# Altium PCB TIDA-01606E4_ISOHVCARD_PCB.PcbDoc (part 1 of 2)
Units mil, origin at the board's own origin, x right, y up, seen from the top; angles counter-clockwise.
Board outline 2900 x 1300 mil, 4 copper layers (Top Layer, Signal Layer 1, Signal Layer 2, Bottom Layer), stack 61.6 mil thick; 82 components, 40 nets, 166 pads, 21 vias.
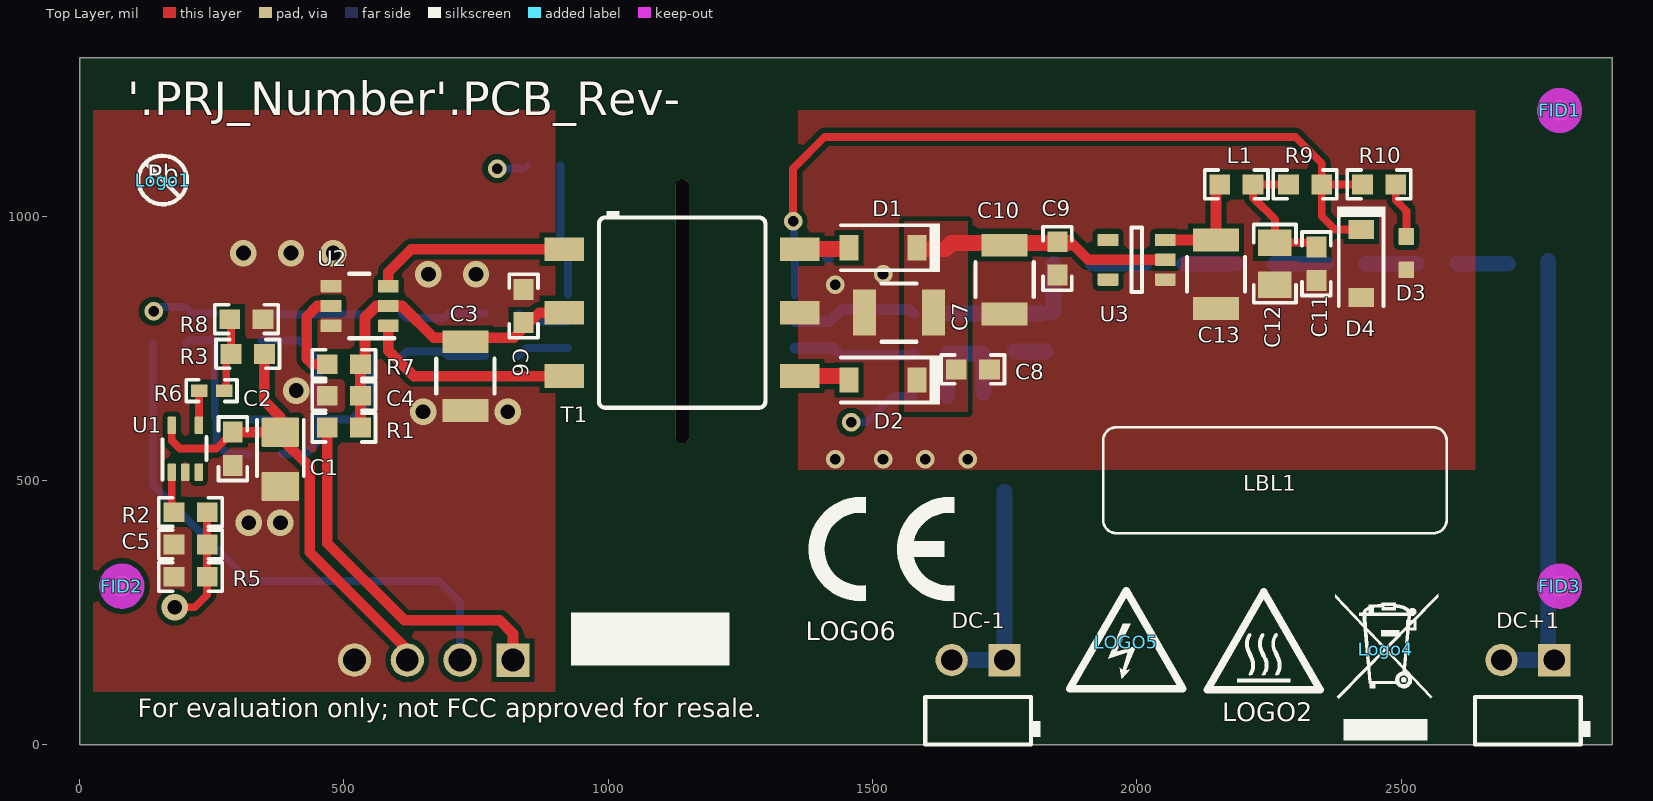
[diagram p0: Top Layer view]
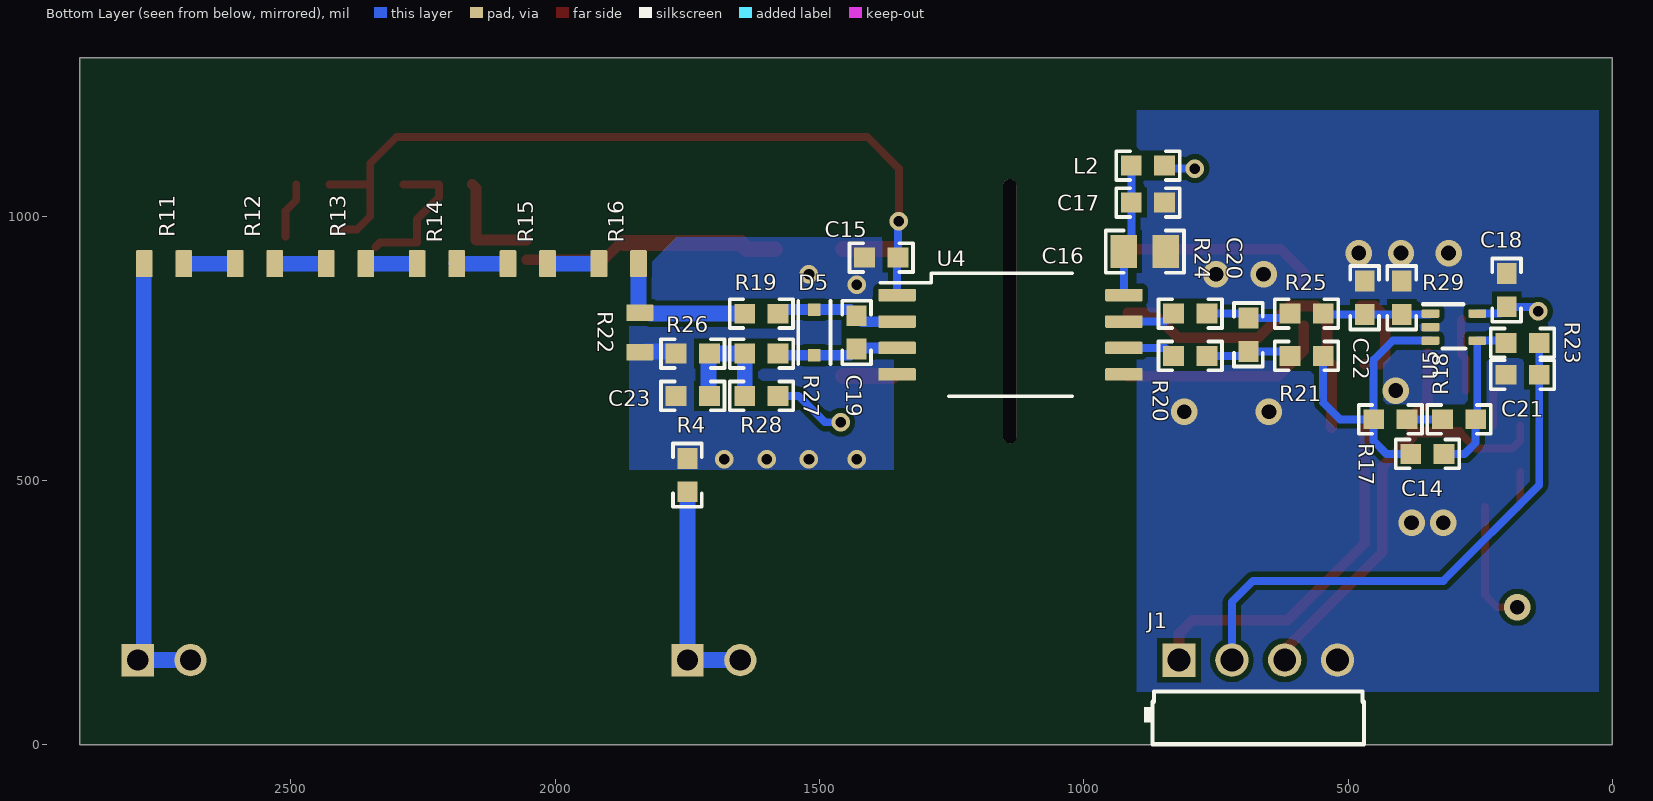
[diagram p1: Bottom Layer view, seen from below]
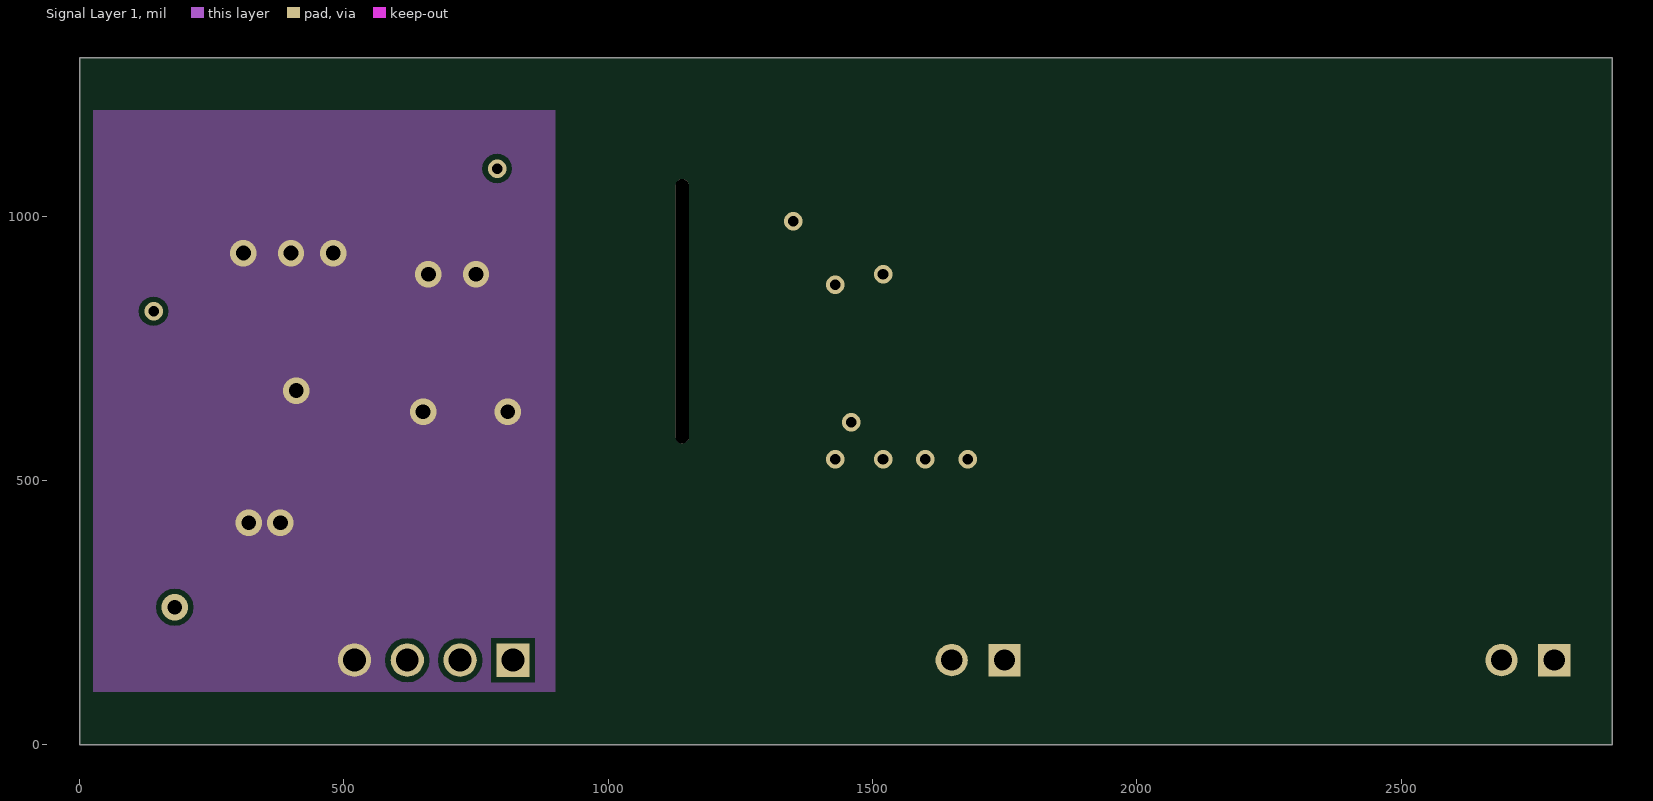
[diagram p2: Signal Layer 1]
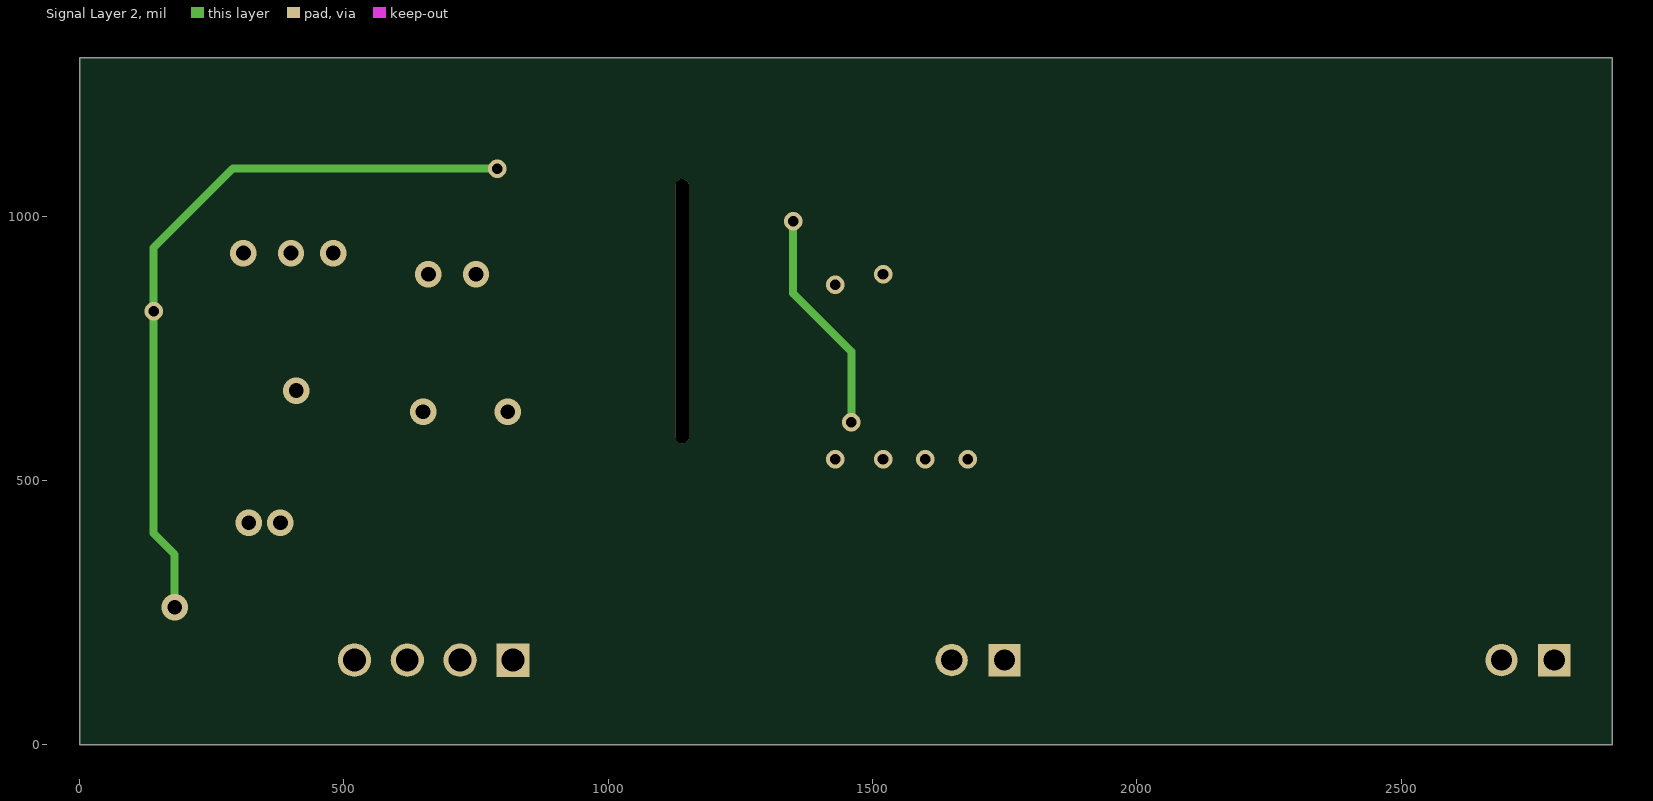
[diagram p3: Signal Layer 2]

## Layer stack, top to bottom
Top Solder: solder mask 0.4, Solder Resist, Dk 3.5
Top Layer: signal copper 1.4
Dielectric 1: prepreg 8, FR-4, Dk 4.2
Signal Layer 1: signal copper 1.4
Dielectric 2: core 40, FR-4, Dk 4.2
Signal Layer 2: signal copper 1.4
Dielectric 3: prepreg 8, FR-4, Dk 4.2
Bottom Layer: signal copper 1.4
Bottom Solder: solder mask 0.4, Solder Resist, Dk 3.5

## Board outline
0,0 2900,0 2900,1300 0,1300

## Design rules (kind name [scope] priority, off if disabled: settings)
AcuteAngle [All] p1: minimum=4.50000000000000E+0001 checktracksonly=FALSE
AssemblyTestPointUsage [All] p1: valid=2
BoardOutlineClearance BoardOutlineClearance_MountingHoles [OnCopper and InComponentClass('Mounting Holes')] p1: gap=40 ignorepadtopadclearanceinfootprint=FALSE
BoardOutlineClearance BoardOutlineClearance_Poly [OnCopper and IsPoly] p2: gap=25 ignorepadtopadclearanceinfootprint=FALSE
BoardOutlineClearance [OnCopper and Not InComponentClass('Logo') and not InComponentClass('FiducialMark') and not InRegion(1000,500,4000,800) and not InPoly] p3: gap=20 ignorepadtopadclearanceinfootprint=FALSE
Clearance Clearance_Keepouts [((IsTrack Or IsArc) And Not InPoly) And IsFree and IsKeepOut vs ((IsTrack Or IsArc) And Not InPoly) And IsFree and IsKeepOut] p1: gap=0 ignorepadtopadclearanceinfootprint=FALSE
Clearance Clearance_Poly [InPolygon] p2: gap=10 ignorepadtopadclearanceinfootprint=FALSE except(0: Arc-Hole Track-Hole SMDPad-Hole THPad-Hole Via-Hole Fill-Hole Poly-Hole Region-Hole Text-Hole)
Clearance Clearance_FiducialMark [IsKeepOut and InComponentClass('FiducialMark') vs IsPad and InComponentClass('FiducialMark')] p3: gap=0 ignorepadtopadclearanceinfootprint=FALSE
Clearance [All] p4: gap=7.87 ignorepadtopadclearanceinfootprint=FALSE except(0: Arc-Hole Track-Hole SMDPad-Hole THPad-Hole Via-Hole Fill-Hole Poly-Hole Region-Hole Text-Hole)
ComponentClearance ComponentClearance_MountingHoles_FiducialMarks [InComponentClass('Mounting Holes') vs InComponentClass('FiducialMark')] p1: gap=50 collisioncheckmode=3 verticalgap=10 showdistances=FALSE
ComponentClearance ComponentClearance_Shunt [InComponentClass('Header') vs InComponentClass('Shunt')] p2: gap=0 collisioncheckmode=3 verticalgap=0 showdistances=FALSE
ComponentClearance ComponentClearance_Logo [InComponentClass('Logo')] p3: gap=50 collisioncheckmode=3 verticalgap=10 showdistances=FALSE
ComponentClearance ComponentClearance_ScrewToNut [(HasFootprint('NY PMS 440 0025 PH')) vs (HasFootprint('Keystone_1902C'))] p4: gap=5 collisioncheckmode=3 verticalgap=10 showdistances=FALSE
ComponentClearance ComponentClearance_MountingHoles [InComponentClass('Mounting Holes')] p5: gap=250 collisioncheckmode=3 verticalgap=100000 showdistances=FALSE
ComponentClearance ComponentClearance_SmallPassives [HasFootprint('0201*') or HasFootprint('0402*') or HasFootprint('0508') or HasFootprint('0603*') or HasFootprint('0612') or HasFootprint('0805*') or HasFootprint('0815*') or HasFootprint('0830*') or HasFootprint('1206*') or HasFootprint('1210*') or HasFootprint('1808*') or HasFootprint('1812*') or HasFootprint('1825*') or HasFootprint('2010*') or HasFootprint('2220*') or HasFootprint('2225*') or HasFootprint('2512*') or HasFootprint('2728*') or HasFootprint('3518*') vs HasFootprint('0201*') or HasFootprint('0402*') or HasFootprint('0508') or HasFootprint('0603*') or HasFootprint('0612') or HasFootprint('0805*') or HasFootprint('0815*') or HasFootprint('0830*') or HasFootprint('1206*') or HasFootprint('1210*') or HasFootprint('1808*') or HasFootprint('1812*') or HasFootprint('1825*') or HasFootprint('2010*') or HasFootprint('2220*') or HasFootprint('2225*') or HasFootprint('2512*') or HasFootprint('2728*') or HasFootprint('3518*')] p6: gap=14.96 collisioncheckmode=3 verticalgap=10 showdistances=FALSE
ComponentClearance ComponentClearance_THtoSMT [IsThruComponent vs IsSMTComponent] p7: gap=40 collisioncheckmode=3 verticalgap=30 showdistances=FALSE
ComponentClearance ComponentClearance_THtoTH [IsThruComponent vs IsThruComponent] p8: gap=30 collisioncheckmode=3 verticalgap=30 showdistances=FALSE
ComponentClearance [All] p9: gap=30 collisioncheckmode=3 verticalgap=10 showdistances=FALSE
DiffPairsRouting [All] p1: maxlimit=100 minlimit=10 mostfreqgap=10 toplayer_minwidth=15 toplayer_maxwidth=15 toplayer_prefwidth=15 midlayer1_minwidth=15 midlayer1_maxwidth=15 midlayer1_prefwidth=15 midlayer2_minwidth=15 midlayer2_maxwidth=15 midlayer2_prefwidth=15 bottomlayer_minwidth=15 bottomlayer_maxwidth=15 bottomlayer_prefwidth=15 maxuncoupledlength=1000
FabricationTestPointUsage TestPointUsage [All] p1: valid=2 allowmultiple=FALSE
FabricationTestpoint Testpoint [All] p1: side=3 testpointundercomponent=TRUE minsize=40 maxsize=100 preferedsize=60 minholesize=0 maxholesize=40 preferedholesize=32 testpointgrid=1 allowsidetop=TRUE allowsidebottom=TRUE usegrid=TRUE gridtolerance=0.01
FanoutControl Fanout_LCC [IsLCC] p1: bgadir=Out bgaviamode=Centered fanoutstyle=Auto fanoutdirection=Alternating viagrid=1 // Fanout_LCC (Default Rule)
FanoutControl Fanout_BGA [IsBGA] p2: bgadir=Out bgaviamode=Centered fanoutstyle=Auto fanoutdirection=Alternating viagrid=1 // Fanout_BGA (Default Rule)
FanoutControl Fanout_Default [All] p4: bgadir=Out bgaviamode=Centered fanoutstyle=Auto fanoutdirection=Alternating viagrid=1 // Fanout_Default (Default Rule)
FanoutControl Fanout_Small [(CompPinCount < 5)] p5: bgadir=Out bgaviamode=Centered fanoutstyle=Auto fanoutdirection=OutThenIn viagrid=1 // Fanout_Small (Default Rule)
HoleSize [All] p1: absolutevalues=TRUE maxlimit=251 minlimit=7.87 maxpercent=80.000 minpercent=20.000
MinimumAnnularRing MinimumAnnularRing_ThermalPadVias [IsVia and InAnyComponent] p1: minimumring=5.91
MinimumAnnularRing [All] p2: minimumring=5.91
MinimumSolderMaskSliver MinimumSolderMaskSliver_Logo [InComponentClass('Logo') vs InComponentClass('Logo')] p1: minsoldermaskwidth=0.7
MinimumSolderMaskSliver [All] p2: minsoldermaskwidth=3.94
PlaneConnect [All] p1: planeconnectstyle=Relief reliefexpansion=10 reliefentries=4 reliefconductorwidth=10 reliefairgap=10
PolygonConnect [All] p1: connectstyle=Direct reliefconductorwidth=10 reliefentries=4 polygonreliefangle="90 Angle" airgapwidth=10
RoutingVias ThermalPadVias [IsVia and InAnyComponent] p1: holewidth=7.87 width=19.68 viastyle="Through Hole" minholewidth=7.87 minwidth=19.68 maxholewidth=12.99 maxwidth=23.62
RoutingVias [All] p2: holewidth=16 width=34 viastyle="Through Hole" minholewidth=7.87 minwidth=26 maxholewidth=40 maxwidth=65 useviatemplates=TRUE viatemplateguid#1={9F31C9FF-2BD5-453B-A82C-7621D56C8CD3} viatemplateguid#2={D5BB49E9-BDCC-478A-8375-7751F0B2134C} viatemplateguid#3={256FE276-3E65-4C8F-AC9F-BFAD4B80671E} viatemplatename#1=v89h51m0mx0 viatemplatename#2=v127h71m0mx0 viatemplatename#3=v61h20m0mx0
SilkToBoardRegionClearance [Not ((IsComment or IsDesignator) And (Hide <> 'False')) and not InRegion(1000,500,4000,800)] p1:
SilkToSilkClearance SilkToSilkClearance_Pb-FreeLogo [(HasFootprint('Pb-Free_Overlay_Medium') OR HasFootprint('Pb-Free_Overlay_Small')) vs (HasFootprint('Pb-Free_Overlay_Medium') OR HasFootprint('Pb-Free_Overlay_Small'))] p1: silktosilkclearance=0
SilkToSilkClearance [All] p2: silktosilkclearance=4
SilkToSolderMaskClearance SilkToComponentPadClearance [(IsPad or IsFill or IsRegion) and InAnycomponent] p1: minsilkscreentomaskgap=5 clearancetoexposedcopper=TRUE
SilkToSolderMaskClearance "Silk to Solder Mask Opening" [All] p2: minsilkscreentomaskgap=4 clearancetoexposedcopper=FALSE
SolderMaskExpansion [All] p1: expansion=1.97 istentingtop=FALSE
Width [All] p1: maxlimit=100 minlimit=6 preferedwidth=10 checkconnectedcopper=TRUE
15 further rules are at their usual default settings.

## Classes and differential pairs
component class TIDA-01606E4_ISOHVCARD_SCH_Pg1: C1 C2 C3 C4 C5 C6 C7 C8 C9 C10 C11 C12 C13 C14 C15 C16 C17 C18 C19 C20 C21 C22 C23 D1 D2 D3 D4 D5 DC+1 DC-1 J1 L1 L2 R1 R2 R3 R4 R5 R6 R7 R8 R9 R10 R11 R12 R13 R14 R15 R16 R17 R18 R19 R20 R21 R22 R23 R24 R25 R26 R27 R28 R29 R110 T1 U1 U2 U3 U4 U5
component class Label: LBL1
component class AssemblyNote: ZZ1 ZZ2 ZZ3 ZZ4
component class FiducialMark: FID1 FID2 FID3
component class TIDA-01606E4_ISOHVCARD_EVM_Hardware_Pg2: FID1 FID2 FID3 LBL1 Logo1 LOGO2 Logo3 Logo4 LOGO5 LOGO6 ZZ1 ZZ2 ZZ3 ZZ4
component class Header: J1

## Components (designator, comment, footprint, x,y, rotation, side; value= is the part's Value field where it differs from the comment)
C1 "TAJA106M010RNJ" 3216-18 380,540 r270 top value=10uF
C2 "885012206095" 0603 290,560 r90 top value=0.1uF
C3 "C3225X7R1H106M250AC" 1210_280 730,697.37 r90 top value=10uF
C4 "885012206095" 0603 500,660 r0 top value=0.1uF
C5 "885012206095" 0603 210,378.79 r0 top value=0.1uF
C6 "885012206095" 0603 840,830 r270 top value=0.1uF
C7 "C3225X7R1H106M250AC" 1210_280 1550.23,817.55 r180 top value=10uF
C8 "885012206095" 0603 1690,710 r0 top value=0.1uF
C9 "885012206095" 0603 1850,920 r270 top value=0.1uF
C10 "C3225X7R1H106M250AC" 1210_280 1750,880 r90 top value=10uF
C11 "885012206095" 0603 2340,910 r270 top value=0.1uF
C12 "GRM21BR61H475KE51L" 0805_HV 2261.4,910 r90 top value=4.7uF
C13 "C3225X7R1H106M250AC" 1210_280 2150,890 r90 top value=10uF
C14 "Capacitor" 0603 350,550 r180 bottom value=0.01uF
C15 "Capacitor" 0603 1383.25,921.55 r180 bottom value=0.1uF
C16 "GRM21BR61H475KE51L" 0805_HV 884.7,933 r0 bottom value=4.7uF
C17 "Capacitor" 0603 878.7,1025.55 r0 bottom value=0.1uF
C18 "Capacitor" 0603 200,860 r90 bottom value=0.1uF
C19 "Capacitor" 0603 1430,780 r270 bottom value=0.01uF
C20 "Capacitor" 0603 688.7,775.55 r90 bottom value=0.01uF
C21 "Capacitor" 0603 170,700 r0 bottom value=0.1uF
C22 "Capacitor" 0603 468.7,845.55 r90 bottom value=0.01uF
C23 "Capacitor" 0603 1740.02,659.97 r180 bottom value=0.1uF
D1 "B0520LW-7-F" SOD-123 1520,940 r180 top value=20V
D2 "B0520LW-7-F" SOD-123 1520,690 r180 top value=20V
D3 "150060VS55040" WL-SMCD-0603 2510,930 r90 top value=Green
D4 "Zener" SOD-123 2424.5,910.14 r270 top value=5.6V
D5 "CDSOD323-T03SC" SOD-323-Bi 1510,780 r90 bottom value=3.3V
DC+1 "PBC02SGBN" Sullins_PxC02SGBN 2740,160 r180 top
DC-1 "PBC02SGBN" Sullins_PxC02SGBN 1700,160 r180 top
FID1 "Fiducial" Fiducial10-20 2800,1200 r0 top
FID2 "Fiducial" Fiducial10-20 80,300 r0 top
FID3 "Fiducial" Fiducial10-20 2800,300 r0 top
J1 "61300411021" Wurth_61300411021 670,160 r180 bottom
L1 "742792662" 0603 2188.5,1060 r0 top value="1000 ohm"
L2 "74279228260" 0603 878.7,1095.55 r180 bottom value="26 ohm"
LBL1 "THT-14-423-10" Label_650x200 2261.4,500.36 r0 top
Logo1 "Pb-Free Symbol" Pb-Free_Overlay_Small 157.23,1068.35 r0 top
LOGO2 "CAUTION HOT SURFACE" IEC_HotSurface_Small 2240,196.71 r0 top
Logo3 "FCC disclaimer" FCC_disclaimer 1150,3380 r0 top
Logo4 "WEEE logo" WEEE_Minimum 2470.86,181 r0 top
LOGO5 "DANGER HIGH VOLTAGE" IEC_HighVoltage_Small 1980.32,194.07 r0 top
LOGO6 "CE Mark" CE_Mark_5mm 1517.34,370 r0 top
R1 "ERJ-3GEY0R00V" 0603 500,600 r180 top value=0
R2 "ERJ-3GEY0R00V" 0603 210,440 r180 top value=0
R3 "Resistor" 0603 318.12,739.26 r0 top value=47k
R4 "ERJ-3GEY0R00V" 0603 1750,510 r90 bottom value=0
R5 "Resistor" 0603 210,317.71 r180 top value=2.20k
R6 "CRCW04020000Z0ED" 0402 250,670 r0 top value=0
R7 "ERJ-3GEY0R00V" 0603 500,720 r180 top value=0
R8 "Resistor" 0603 315.72,805.09 r180 top value=47k
R9 "ERJ-3GEY0R00V" 0603 2318.5,1060 r0 top value=0
R10 "RC0603JR-07330RL" 0603 2458.5,1060 r0 top value=330
R11 "MMU01020C3323FB300" MMU_0102 2740,910 r0 bottom value=332k
R12 "MMU01020C3323FB300" MMU_0102 2568,910 r0 bottom value=332k
R13 "MMU01020C3323FB300" MMU_0102 2396,910 r0 bottom value=332k
R14 "MMU01020C3323FB300" MMU_0102 2224,910 r0 bottom value=332k
R15 "MMU01020C3323FB300" MMU_0102 2052,910 r0 bottom value=332k
R16 "MMU01020C3323FB300" MMU_0102 1880,910 r0 bottom value=332k
R17 "Resistor" 0603 420.2,615.55 r180 bottom value=0
R18 "Resistor" 0603 290.2,615.55 r0 bottom value=15.0k
R19 "Resistor" 0603 1610.21,815.52 r180 bottom value=39
R20 "Resistor" 0603 798.7,735.55 r180 bottom value=4.70k
R21 "Resistor" 0603 578.7,735.55 r180 bottom value=4.70k
R22 "MMU01020C3601FB300" MMU_0102 1840,780 r90 bottom value=3.60k
R23 "ERJ-3EKF1000V" 0603 170,760 r180 bottom value=100
R24 "Resistor" 0603 798.7,815.55 r180 bottom value=4.70k
R25 "Resistor" 0603 578.7,815.55 r180 bottom value=4.70k
R26 "ERJ-3GEY0R00V" 0603 1740.02,739.97 r180 bottom value=0
R27 "Resistor" 0603 1610.02,739.97 r180 bottom value=39
R28 "Resistor" 0603 1610.02,659.97 r0 bottom value=31.6k
R29 "Resistor" 0603 398.7,845.55 r270 bottom value=15.0k
T1 "750313638" Wurth_750313638 1140,817.45 r0 top value=340uH
U1 "TI-TPS22944DCK5" DCK0005A_N 200,560 r90 top
U2 "SN6505" DBV0006A_N 530,830 r180 top
U3 "TLV70433DBVT" DBV0005A_N 2000,917.45 r180 top
U4 "AMC1311DWVR" DWV0008A 1138.7,775.55 r180 bottom
U5 "PTLV9061IDCKR" DCK0005A_N 300,790 r180 bottom
ZZ1 "This Assembly Note is for PCB labels only" AssemblyNoteLabel -1015,3938 r0 top
ZZ2 "These assemblies are ESD sensitive, ESD precautions shall be observed." AssemblyNote -1015,3829.11 r0 top
ZZ3 "These assemblies must be clean and free from flux and all contaminants. Use of no clean flux is not acceptable." AssemblyNote -1015,3740.56 r0 top
ZZ4 "These assemblies must comply with workmanship standards IPC-A-610 Class 2, unless otherwise specified." AssemblyNote -1015,3652 r0 top

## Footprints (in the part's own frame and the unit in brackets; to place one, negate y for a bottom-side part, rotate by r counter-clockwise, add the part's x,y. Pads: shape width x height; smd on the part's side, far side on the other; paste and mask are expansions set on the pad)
0402 [mm] "0402 from SM-752 data"
  rect 0.8x0.6 smd: 1(-0.6,0) 2(0.6,0)
  silkscreen extent -1.22,-0.52 1.22,0.52, body extent -0.55,-0.3 0.55,0.3, height 0.6
0603 [mm] "0603 from SM-752 data"
  rect 1x0.95 smd: 1(-0.8,0) 2(0.8,0)
  silkscreen extent -1.52,-0.69 1.52,0.69, body extent -0.87,-0.47 0.87,0.47, height 1
0805_HV [mil] "0805 with 30mil clearance between pads"
  rect 50x63 smd: 1(-40,0) 2(40,0)
  silkscreen extent -74,-40 74,40, body extent -43,-29 43,29, height 57
1210_280 [mm] "SMD, 2-Leads, Body 3.6x2.8mm, Height 2.8mm"
  rect 1.1x2.2 smd: 1(-1.65,0) 2(1.65,0)
  silkscreen extent -0.84,-1.4 0.84,1.4, body extent -1.8,-1.4 1.8,1.4, height 2.8
3216-18 [mm] "Based on AVX recommendation in http://www.avx.com/download/software/literature/AVX-Footprint-Library.pdf"
  rrect7% 1.4x1.8 smd: 1(-1.3,0) 2(1.3,0)
  silkscreen extent -1.9,-1.12 0.8,1.12, body extent -1.7,-0.9 1.7,0.9, height 1.82
AssemblyNote [mil] "Assembly Note"
AssemblyNoteLabel [mil] "Assembly Note for PCB Labels"
CE_Mark_5mm [mil] "Minimum text height for CE Mark"
  silkscreen extent -138,-98 138,98
DBV0005A_N [mm] "SOT23, 5-Leads, Body 2.9x1.6mm, Pitch 0.95mm, Lead Span 2.8mm, IPC Medium Density"
  rrect17% 1x0.6 smd: 1(-1.375,0.95) 2(-1.375,0) 3(-1.375,-0.95) 4(1.375,-0.95) 5(1.375,0.95)
  silkscreen extent -0.25,-1.55 0.25,1.55, body extent -1.42,-1.46 1.42,1.46, height 1.09
DBV0006A_N [mm] "SOT23, 6-Leads, Body 2.9x1.6mm, Pitch 0.95mm, Lead Span 2.8mm, IPC Medium Density"
  rrect17% 1x0.6 smd: 1(-1.375,0.95) 2(-1.375,0) 3(-1.375,-0.95) 4(1.375,-0.95) 5(1.375,0) 6(1.375,0.95)
  silkscreen extent -1.68,-1.55 0.5,1.55, body extent -1.42,-1.46 1.42,1.46, height 1.12
DCK0005A_N [mm] "SOT353, 5-Leads, Body 2x1.3mm, Pitch 0.65mm, Lead Span 2.1mm, IPC Medium Density"
  rrect25% 0.85x0.4 smd: 1(-1.125,0.65) 2(-1.125,0) 3(-1.125,-0.65) 4(1.125,-0.65) 5(1.125,0.65)
  silkscreen extent -1.48,-1.02 0.55,1.1, body extent -1.14,-1 1.14,1, height 0.95
DWV0008A [mm] "SOIC, 8-Leads, Body 5.95x7.6mm (max), Pitch 1.27mm"
  rrect17% 1.8x0.6 smd: 1(-5.45,1.905) 2(-5.45,0.635) 3(-5.45,-0.635) 4(-5.45,-1.905) 5(5.45,-1.905) 6(5.45,-0.635) 7(5.45,0.635) 8(5.45,1.905)
  silkscreen extent -6.25,-2.95 2.98,2.95, body extent -5.77,-2.92 5.77,2.93, height 2.67
FCC_disclaimer [mil]
Fiducial10-20 [mm]
  round 1 smd mask+0.5: 1(0,0)
  Top Layer keep-out circle w1.178: c0,0 r0.5
IEC_HighVoltage_Small [mil]
  silkscreen extent -107,-88 107,97
IEC_HotSurface_Small [mil]
  silkscreen extent -107,-93 107,92
Label_650x200 [mil] "Thermal Transfer Label"
  round 1 on Mech13: 0(0,0)
  silkscreen extent -325,-100 325,100, body extent -325,-100 325,100, height 1
MMU_0102 [mm] "SMD, 2-Leads, Body 2.2x1.1mm"
  rrect12% 0.8x1.3 smd: 1(-0.95,0) 2(0.95,0)
  body extent -1.1,-0.55 1.1,0.55, height 1.1
Pb-Free_Overlay_Small [mil]
  silkscreen extent -46,-46 46,46
SOD-123 [mm] "On Semi recommended land pattern"
  rect 0.915x1.22 smd: 1(-1.637,0) 2(1.637,0)
  silkscreen extent -2.74,-1.17 2.03,1.17, body extent -1.93,-0.9 1.93,0.9, height 1.35
SOD-323-Bi [mm] "SOD323, 2-Leads, Body 1.9x1.45mm, No Polarity Mark"
  rect 0.6x0.6 smd paste-0.05: 1(-1.1,0) 2(1.1,0)
  silkscreen extent -1.53,-0.77 1.53,0.77, body extent -1.27,-0.65 1.27,0.65, height 1.02
Sullins_PxC02SGBN [mm] "Header, 2.54mm, 2x1, R/A, TH"
  rect 1.55x1.55 hole 1.016: 1(-1.27,0)
  round 1.55 hole 1.016: 2(1.27,0)
  silkscreen extent -3,1.77 2.54,4.06, body extent -2.54,-0.32 2.54,12.14, height 3.56
WEEE_Minimum [mil] "WEEElie bin"
  silkscreen extent -95,-172 99,104
WL-SMCD-0603 [mm] "SMD, 2-Leads, Body 1.6x0.8mm"
  rrect13% 0.8x0.75 smd: 1(-0.8,0) 2(0.8,0)
  body extent -0.8,-0.4 0.8,0.4, height 0.4
Wurth_750313638 [mm] "SMD, 6-Leads, Body 8x9.14mm, Pitch 3.05mm"
  rect 1.9x1.14 smd: 1(-5.655,3.05) 2(-5.655,0) 3(-5.655,-3.05) 4(5.655,-3.05) 5(5.655,0) 6(5.655,3.05)
  silkscreen extent -4,-4.57 4,4.87, body extent -6.35,-4.57 6.35,4.57, height 7.62
Wurth_61300411021 [mm] "Header, 2.54 mm, 4x1, R/A, TH"
  rect 1.6x1.6 hole 1.1: 1(-3.81,0)
  round 1.6 hole 1.1: 2(-1.27,0) 3(1.27,0) 4(3.81,0)
  silkscreen extent -5.5,-4.04 5.08,-1.5, body extent -5.08,-10.04 5.08,0.32, height 2.55

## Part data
C1: library part CMP-0011478-2, "CAP, TA, 10 uF, 10 V, +/- 20%, 3 ohm, SMD", Cap_Case=3216-18, Manufacturer=AVX, Supplier Part Number 1=478-1657-1-ND, Tolerance_%=20%, Value1="3 ohm", Value2=10V, ValueDisplayed=10uF
C2 C4 C5 C6 C8 C9 C11: library part CMP-0006837-4, "CAP, CERM, 0.1 uF, 50 V, +/- 10%, X7R, 0603", Cap_Case=0603, Manufacturer="Wurth Elektronik", TempCo=X7R, Tolerance_%=10%, Value1=Unknown, Value2=50V, ValueDisplayed=0.1uF
C3 C7 C10 C13: library part CMP-0009120-1, "CAP, CERM, 10 uF, 50 V, +/- 20%, X7R, 1210", Cap_Case=1210, Manufacturer=TDK, Supplier Part Number 1=445-14933-1-ND, TempCo=X7R, Tolerance_%=20%, Value1=Unknown, Value2=50V, ValueDisplayed=10uF
C12 C16: library part CMP-0008309-2, "CAP, CERM, 4.7 uF, 50 V, +/- 10%, X5R, 0805", Cap_Case=0805, Manufacturer=MuRata, Supplier Part Number 1=GRM21BR61H475KE51L-ND, TempCo=X5R, Tolerance_%=10%, Value1=Unknown, Value2=50V, ValueDisplayed=4.7uF
C14 C19 C20 C22: library part CMP-0006828-4, "CAP, CERM, 0.01 uF, 16 V, +/- 10%, X7R, 0603", Cap_Case=0603, Manufacturer="Wurth Elektronik", PartNumber=885012206040, Supplier Part Number 1=732-7959-1-ND, TempCo=X7R, Tolerance_%=10%, Value1=Unknown, Value2=16V, ValueDisplayed=0.01uF
C15 C17 C18 C21 C23: library part CMP-0007434-4, "CAP, CERM, 0.1 uF, 50 V, +/- 10%, X7R, 0603", Cap_Case=0603, Manufacturer=MuRata, PartNumber=GRM188R71H104KA93D, Supplier Part Number 1=490-1519-1-ND, TempCo=X7R, Tolerance_%=10%, Value1=Unknown, Value2=50V, ValueDisplayed=0.1uF
D1 D2: library part CMP-0080707-1, "Diode, Schottky, 20 V, 0.5 A, SOD-123", Manufacturer="Diodes Inc.", Supplier Part Number 1=B0520LW-FDICT-ND, Value1=0.5A, Value2=0.33V
D3: library part CMP-0081648-1, "LED, Green, SMD", Color=Green, Manufacturer="Wurth Elektronik", Power_TotalModule=48mW, Supplier Part Number 1=732-12017-1-ND, Value1=0.048W, Value2=2V
D4: library part CMP-0005803-1, "Diode, Zener, 5.6 V, 500 mW, SOD-123", Manufacturer="Diodes Inc.", PartNumber=MMSZ5232B-7-F, Power_W=500mW, Supplier Part Number 1=MMSZ5232B-FDICT-ND, Value1=0.5W
D5: library part CMP-0006063-1, "Diode, TVS, Bi, 3.3 V, 10.9 Vc, SOD323, 2-Leads, Body 1.9x1.45mm, No Polarity Mark", Manufacturer=Bourns, Supplier Part Number 1=CDSOD323-T03SCCT-ND, Value1=W
DC+1 DC-1: library part CMP-0054714-1, "Header, 2.54 mm, 2x1, Gold, R/A, TH", Color=Black, Current_A=3A, Manufacturer="Sullins Connector Solutions", Supplier Part Number 1=S1321E-02-ND, Voltage_V=1.8kV
FID1 FID2 FID3: library part CMP-0077181-1, "Fiducial mark.  There is nothing to buy or mount.", Manufacturer=N/A
J1: library part CMP-0054797-1, "Header, 2.54 mm, 4x1, Gold, R/A, TH", Color=Black, Manufacturer="Wurth Elektronik", Supplier Part Number 1=732-5337-ND
L1: library part CMP-0003201-2, "Ferrite Bead, 1000 ohm @ 100 MHz, 0.6 A, 0603", Manufacturer="Wurth Elektronik", Supplier Part Number 1=732-4670-1-ND, Value1="0.3 ohm", Value2=0.6A, ValueDisplayed="1000 ohm"
L2: library part CMP-0003155-2, "Ferrite Bead, 26 ohm @ 100 MHz, 6.5 A, 0603", Manufacturer="Wurth Elektronik", Supplier Part Number 1=732-6117-1-ND, Value1="0.005 ohm", Value2=6.5A, ValueDisplayed="26 ohm"
LBL1: library part CMP-0003625-1, "Thermal Transfer Printable Labels, 0.650\" W x 0.200\" H - 10,000 per roll", Manufacturer=Brady, Supplier Part Number 1=97C5133
Logo1: library part CMP-0074839-1
LOGO2: library part CMP-0074837-1, "IEC 61010-1 Hot Surface Warning"
Logo3: library part CMP-0074847-1, "FCC_disclaimer"
Logo4: library part CMP-0074769-1
LOGO5: library part CMP-0074835-1, "IEC 61010-1 High Voltage Warning"
LOGO6: library part CMP-0074844-1
R1 R2 R4 R7 R9 R26: library part CMP-0025874-4, "RES, 0, 5%, 0.1 W, AEC-Q200 Grade 0, 0603", Manufacturer=Panasonic, Power_W=100mW, Supplier Part Number 1=P0.0GCT-ND, TempCo="600 ppm/C", Tolerance_%=5%, Value2=0.1W, Value_Code=0000, ValueDisplayed=0
R3 R8: library part CMP-0025925-5, "RES, 47 k, 5%, 0.1 W, 0603", Manufacturer=Yageo, PartNumber=RC0603JR-0747KL, Power_W=100mW, Supplier Part Number 1=311-47KGRCT-ND, TempCo="100 ppm/C", Tolerance_%=5%, Value2=0.1W, Value_Code=47k0, ValueDisplayed=47k
R5: library part CMP-0022986-5, "RES, 2.20 k, 1%, 0.1 W, 0603", Manufacturer=Yageo, PartNumber=RC0603FR-072K2L, Power_W=100mW, Supplier Part Number 1=311-2.20KHRCT-ND, TempCo="100 ppm/C", Tolerance_%=1%, Value2=0.1W, Value_Code=2k20, ValueDisplayed=2.20k
R6: library part CMP-0026822-3, "RES, 0, 5%, 0.063 W, AEC-Q200 Grade 0, 0402", Manufacturer=Vishay-Dale, Power_W=63mW, Supplier Part Number 1=541-0.0JCT-ND, TempCo="200 ppm/C", Tolerance_%=5%, Value2=0.063W, Value_Code=0000, ValueDisplayed=0
R10: library part CMP-0025912-5, "RES, 330, 5%, 0.1 W, 0603", Manufacturer=Yageo, Power_W=100mW, Supplier Part Number 1=311-330GRCT-ND, TempCo="100 ppm/C", Tolerance_%=5%, Value2=0.1W, Value_Code=330R, ValueDisplayed=330
R11 R12 R13 R14 R15 R16: library part CMP-0083757-2, "RES, 332 k, 1%, 0.2 W, AEC-Q200 Grade 0, 2.2x1.1mm", Manufacturer=Vishay-Semiconductor, Power_W=200mW, TempCo="50 ppm/C", Tolerance_%=1%, Value2=0.2W, Value_Code=332k
R17: library part CMP-0025874-4, "RES, 0, 5%, 0.1 W, AEC-Q200 Grade 0, 0603", Manufacturer=Panasonic, PartNumber=ERJ-3GEY0R00V, Power_W=100mW, Supplier Part Number 1=P0.0GCT-ND, TempCo="600 ppm/C", Tolerance_%=5%, Value2=0.1W, Value_Code=0000, ValueDisplayed=0
R18 R29: library part CMP-0022816-5, "RES, 15.0 k, 1%, 0.1 W, 0603", Manufacturer=Yageo, PartNumber=RC0603FR-0715KL, Power_W=100mW, Supplier Part Number 1=311-15.0KHRCT-ND, TempCo="100 ppm/C", Tolerance_%=1%, Value2=0.1W, Value_Code=15k0, ValueDisplayed=15.0k
R19 R27: library part CMP-0025795-4, "RES, 39, 5%, 0.1 W, AEC-Q200 Grade 0, 0603", Manufacturer=Vishay-Dale, PartNumber=CRCW060339R0JNEA, Power_W=100mW, Supplier Part Number 1=541-39GCT-ND, TempCo="200 ppm/C", Tolerance_%=5%, Value2=0.1W, Value_Code=39R0, ValueDisplayed=39
R20 R21 R24 R25: library part CMP-0023153-5, "RES, 4.70 k, 1%, 0.1 W, 0603", Manufacturer=Yageo, PartNumber=RC0603FR-074K7L, Power_W=100mW, Supplier Part Number 1=311-4.70KHRCT-ND, TempCo="100 ppm/C", Tolerance_%=1%, Value2=0.1W, Value_Code=4k70, ValueDisplayed=4.70k
R22: library part CMP-0083758-2, "RES, 3.60 k, 1%, 0.3 W, AEC-Q200 Grade 0, 2.2x1.1mm", Manufacturer=Vishay-Semiconductor, Power_W=300mW, TempCo="50 ppm/C", Tolerance_%=1%, Value2=0.3W, Value_Code=3k60, ValueDisplayed=3.60k
R23: library part CMP-0022679-3, "RES, 100, 1%, 0.1 W, AEC-Q200 Grade 0, 0603", Manufacturer=Panasonic, Power_W=100mW, Supplier Part Number 1=P100HCT-ND, TempCo="100 ppm/C", Tolerance_%=1%, Value2=0.1W, Value_Code=100R, ValueDisplayed=100
R28: library part CMP-0022330-4, "RES, 31.6 k, 1%, 0.1 W, AEC-Q200 Grade 0, 0603", Manufacturer=Vishay-Dale, PartNumber=CRCW060331K6FKEA, Power_W=100mW, Supplier Part Number 1=541-31.6KHCT-ND, TempCo="100 ppm/C", Tolerance_%=1%, Value2=0.1W, Value_Code=31k6, ValueDisplayed=31.6k
T1: library part CMP-0030601-1, "Transformer, 340 uH, SMT", Manufacturer="Wurth Elektronik", Supplier Part Number 1=1297-1105-1-ND, ValueDisplayed=340uH
U1: library part CMP-0034371-2, "Low-Input Voltage 100 mA Current Limited Load Switch, 400 mOhms rDS(On), -40 to 85 degC, 5-pin SC70 (DCK), Green (RoHS & no Sb/Br)", Adjustable Current Limit(Min)(A)=0.1, Manufacturer="Texas Instruments", PartNumber=TPS22944DCKR
U2: library part CMP-0076095-1, "Low-Noise 1 A, 420 kHz Transformer Driver, DBV0006A (SOT-23-6)", Alternate Manufacturer="Texas Instruments", Alternate PartNumber=SN6505BDBVT, PartNumber=SN6505BDBVR
U3: library part CMP-0035592-1, "Single Output LDO, 150 mA, Fixed 3.3 V Output, 2.5 to 24 V Input, with Ultra-Low IQ, 5-pin SOT-23 (DBV), -40 to 125 degC, Green (RoHS & no Sb/Br)", Manufacturer="Texas Instruments"
U4: library part CMP-0013503-2, "Precision, 2-V Input, Reinforced Isolated Amplifier, DWV0008A (SOIC-8)", Alternate Manufacturer="Texas Instruments", Alternate PartNumber=AMC1311DWV
U5: library part CMP-0084061-1, "World's Smallest Amp 10MHz, RRIO, 1.8V-5.5V op-amp delivers high performance for challenging systems, DCK0005A (SOT-SC70-5)", Alternate Manufacturer="Texas Instruments", Operating Temperature Range="-40 to 125 C", Rating=Catalog
ZZ1: library part CMP-0003616-3
ZZ2: library part CMP-0077236-1
ZZ3: library part CMP-0077237-1
ZZ4: library part CMP-0077238-1

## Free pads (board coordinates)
  oval 25x500 hole 25 slot 500 at 90 deg unplated mask+8: 1(1140,820)

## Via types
v1: diameter 50, hole 28, Top Layer to Bottom Layer, tented both sides, 11 vias
v2: diameter 35, hole 20, Top Layer to Bottom Layer, tented both sides, 10 vias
